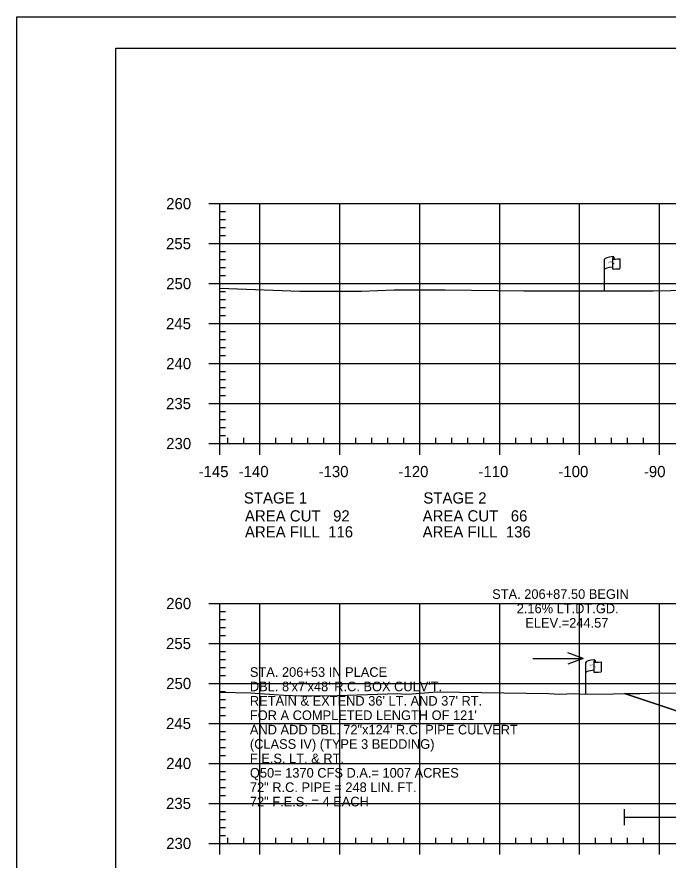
# Model space of a CAD drawing. Extents: x 1365647 to 1367999, y 387113 to 400173.
# Drawn here: x 1365723.7 to 1365805.2, y 390254 to 390359.5 of the extents above; entities that cross this region are included whole.
import ezdxf

# ---------------------------------------------------------------- set-up
doc = ezdxf.new("R2010")
doc.units = 0
for name, color, linetype in [('E_Existing ROW', 7, 'Continuous'), ('R_Axis', 7, 'Continuous'), ('R_Axis Annot', 7, 'Continuous'), ('R_Border', 7, 'Continuous'), ('R_Contours', 7, 'Continuous'), ('R_Draft', 7, 'Continuous'), ('R_Exist Surface', 7, 'Continuous'), ('R_Fin Surface', 7, 'Continuous'), ('R_Grid', 7, 'Continuous'), ('R_No Plot', 7, 'Continuous'), ('R_Proposed Const Limits', 7, 'Continuous'), ('R_Water', 7, 'Continuous'), ('R_Water Annot', 7, 'Continuous')]:
    doc.layers.add(name, color=color, linetype=linetype)

msp = doc.modelspace()

# ---------------------------------------------------------------- linework, layer by layer
at = {"layer": 'E_Existing ROW'}
for p, q in [((1365798.2, 390329.26), (1365798.2, 390329.24)), ((1365798.2, 390329.24), (1365798.2, 390328.02)), ((1365798.36, 390329.41), (1365798.36, 390329.17)), ((1365799.13, 390329.22), (1365799.13, 390327.98)), ((1365797.2, 390325.21), (1365797.2, 390329.16)), ((1365794.85, 390274.8), (1365794.85, 390278.75)), ((1365795.85, 390278.84), (1365795.85, 390278.83)), ((1365795.85, 390278.83), (1365795.85, 390277.6)), ((1365796.02, 390279), (1365796.02, 390278.76)), ((1365796.78, 390278.81), (1365796.78, 390277.57))]:
    msp.add_line(p, q, dxfattribs=at)
for centre, radius, start, end in [((1365798.27, 390329.26), 0.078, 88.6458, 274.2828), ((1365798.29, 390329.41), 0.0783, 263.0712, 93.9564), ((1365798.27, 390328.02), 0.0783, 180, 273.9564), ((1365795.93, 390278.85), 0.078, 88.6458, 274.2828), ((1365795.94, 390279), 0.0783, 263.0712, 93.9564), ((1365795.93, 390277.6), 0.0783, 180, 273.9564)]:
    msp.add_arc(centre, radius, start, end, dxfattribs=at)
for centre, major_axis, ratio, start_param, end_param in [((1365798.78, 390329.2), (-1.58, -0.04), 0.19887, 5.030368, 6.283185), ((1365799.49, 390329.32), (-1.23, -0.13), 0.052933, 0.159456, 1.268315), ((1365798.78, 390327.89), (-1.58, -0.04), 0.19887, 5.083035, 6.194897), ((1365799.49, 390328.08), (-1.23, -0.13), 0.052933, 0.159456, 1.268315), ((1365796.44, 390278.79), (-1.58, -0.04), 0.19887, 5.030368, 6.283185), ((1365797.14, 390278.91), (-1.23, -0.13), 0.052933, 0.159456, 1.268315), ((1365796.43, 390277.48), (-1.58, -0.04), 0.19887, 5.083035, 6.194897), ((1365797.14, 390277.67), (-1.23, -0.13), 0.052933, 0.159456, 1.268315)]:
    msp.add_ellipse(centre, major_axis=major_axis, ratio=ratio, start_param=start_param, end_param=end_param, dxfattribs=at)
at = {"layer": 'R_Axis'}
for p, q in [((1365747.69, 390336.11), (1365749.09, 390336.11)), ((1365749.09, 390306.11), (1365749.09, 390336.11)), ((1365749.09, 390335.11), (1365749.79, 390335.11)), ((1365749.09, 390334.11), (1365749.79, 390334.11)), ((1365749.09, 390333.11), (1365749.79, 390333.11)), ((1365749.09, 390332.11), (1365749.79, 390332.11)), ((1365747.69, 390331.11), (1365749.09, 390331.11)), ((1365749.09, 390330.11), (1365749.79, 390330.11)), ((1365749.09, 390329.11), (1365749.79, 390329.11)), ((1365749.09, 390328.11), (1365749.79, 390328.11)), ((1365749.09, 390327.11), (1365749.79, 390327.11)), ((1365747.69, 390326.11), (1365749.09, 390326.11)), ((1365749.09, 390325.11), (1365749.79, 390325.11)), ((1365749.09, 390324.11), (1365749.79, 390324.11)), ((1365749.09, 390323.11), (1365749.79, 390323.11)), ((1365749.09, 390322.11), (1365749.79, 390322.11)), ((1365747.69, 390321.11), (1365749.09, 390321.11)), ((1365749.09, 390320.11), (1365749.79, 390320.11)), ((1365749.09, 390319.11), (1365749.79, 390319.11)), ((1365749.09, 390318.11), (1365749.79, 390318.11)), ((1365749.09, 390317.11), (1365749.79, 390317.11)), ((1365747.69, 390316.11), (1365749.09, 390316.11)), ((1365749.09, 390315.11), (1365749.79, 390315.11)), ((1365749.09, 390314.11), (1365749.79, 390314.11)), ((1365749.09, 390313.11), (1365749.79, 390313.11)), ((1365749.09, 390312.11), (1365749.79, 390312.11)), ((1365747.69, 390311.11), (1365749.09, 390311.11)), ((1365749.09, 390310.11), (1365749.79, 390310.11)), ((1365749.09, 390309.11), (1365749.79, 390309.11)), ((1365749.09, 390308.11), (1365749.79, 390308.11)), ((1365749.09, 390307.11), (1365749.79, 390307.11)), ((1365747.69, 390306.11), (1365749.09, 390306.11)), ((1365749.09, 390306.11), (1365749.09, 390306.81)), ((1365749.09, 390306.11), (1366039.09, 390306.11)), ((1365749.09, 390304.71), (1365749.09, 390306.11)), ((1365750.09, 390306.11), (1365750.09, 390306.81)), ((1365752.09, 390306.11), (1365752.09, 390306.81)), ((1365754.09, 390304.71), (1365754.09, 390306.11)), ((1365756.09, 390306.11), (1365756.09, 390306.81)), ((1365758.09, 390306.11), (1365758.09, 390306.81)), ((1365760.09, 390306.11), (1365760.09, 390306.81)), ((1365762.09, 390306.11), (1365762.09, 390306.81)), ((1365764.09, 390304.71), (1365764.09, 390306.11)), ((1365766.09, 390306.11), (1365766.09, 390306.81)), ((1365768.09, 390306.11), (1365768.09, 390306.81)), ((1365770.09, 390306.11), (1365770.09, 390306.81)), ((1365772.09, 390306.11), (1365772.09, 390306.81)), ((1365774.09, 390304.71), (1365774.09, 390306.11)), ((1365776.09, 390306.11), (1365776.09, 390306.81)), ((1365778.09, 390306.11), (1365778.09, 390306.81)), ((1365780.09, 390306.11), (1365780.09, 390306.81)), ((1365782.09, 390306.11), (1365782.09, 390306.81)), ((1365784.09, 390304.71), (1365784.09, 390306.11)), ((1365786.09, 390306.11), (1365786.09, 390306.81)), ((1365788.09, 390306.11), (1365788.09, 390306.81)), ((1365790.09, 390306.11), (1365790.09, 390306.81)), ((1365792.09, 390306.11), (1365792.09, 390306.81)), ((1365794.09, 390304.71), (1365794.09, 390306.11)), ((1365796.09, 390306.11), (1365796.09, 390306.81)), ((1365798.09, 390306.11), (1365798.09, 390306.81)), ((1365800.09, 390306.11), (1365800.09, 390306.81)), ((1365802.09, 390306.11), (1365802.09, 390306.81)), ((1365804.09, 390304.71), (1365804.09, 390306.11)), ((1365747.69, 390286.11), (1365749.09, 390286.11)), ((1365749.09, 390256.11), (1365749.09, 390286.11)), ((1365749.09, 390285.11), (1365749.79, 390285.11)), ((1365749.09, 390284.11), (1365749.79, 390284.11)), ((1365749.09, 390283.11), (1365749.79, 390283.11)), ((1365749.09, 390282.11), (1365749.79, 390282.11)), ((1365747.69, 390281.11), (1365749.09, 390281.11)), ((1365749.09, 390280.11), (1365749.79, 390280.11)), ((1365749.09, 390279.11), (1365749.79, 390279.11)), ((1365749.09, 390278.11), (1365749.79, 390278.11)), ((1365749.09, 390277.11), (1365749.79, 390277.11)), ((1365747.69, 390276.11), (1365749.09, 390276.11)), ((1365749.09, 390275.11), (1365749.79, 390275.11)), ((1365749.09, 390274.11), (1365749.79, 390274.11)), ((1365749.09, 390273.11), (1365749.79, 390273.11)), ((1365749.09, 390272.11), (1365749.79, 390272.11)), ((1365747.69, 390271.11), (1365749.09, 390271.11)), ((1365749.09, 390270.11), (1365749.79, 390270.11)), ((1365749.09, 390269.11), (1365749.79, 390269.11)), ((1365749.09, 390268.11), (1365749.79, 390268.11)), ((1365749.09, 390267.11), (1365749.79, 390267.11)), ((1365747.69, 390266.11), (1365749.09, 390266.11)), ((1365749.09, 390265.11), (1365749.79, 390265.11)), ((1365749.09, 390264.11), (1365749.79, 390264.11)), ((1365749.09, 390263.11), (1365749.79, 390263.11)), ((1365749.09, 390262.11), (1365749.79, 390262.11)), ((1365747.69, 390261.11), (1365749.09, 390261.11)), ((1365749.09, 390260.11), (1365749.79, 390260.11)), ((1365749.09, 390259.11), (1365749.79, 390259.11)), ((1365749.09, 390258.11), (1365749.79, 390258.11)), ((1365749.09, 390257.11), (1365749.79, 390257.11)), ((1365749.09, 390256.11), (1365749.09, 390256.81)), ((1365750.09, 390256.11), (1365750.09, 390256.81)), ((1365752.09, 390256.11), (1365752.09, 390256.81)), ((1365756.09, 390256.11), (1365756.09, 390256.81)), ((1365758.09, 390256.11), (1365758.09, 390256.81)), ((1365760.09, 390256.11), (1365760.09, 390256.81)), ((1365762.09, 390256.11), (1365762.09, 390256.81)), ((1365766.09, 390256.11), (1365766.09, 390256.81)), ((1365768.09, 390256.11), (1365768.09, 390256.81)), ((1365770.09, 390256.11), (1365770.09, 390256.81)), ((1365772.09, 390256.11), (1365772.09, 390256.81)), ((1365776.09, 390256.11), (1365776.09, 390256.81)), ((1365778.09, 390256.11), (1365778.09, 390256.81)), ((1365780.09, 390256.11), (1365780.09, 390256.81)), ((1365782.09, 390256.11), (1365782.09, 390256.81)), ((1365786.09, 390256.11), (1365786.09, 390256.81)), ((1365788.09, 390256.11), (1365788.09, 390256.81)), ((1365790.09, 390256.11), (1365790.09, 390256.81)), ((1365792.09, 390256.11), (1365792.09, 390256.81)), ((1365796.09, 390256.11), (1365796.09, 390256.81)), ((1365798.09, 390256.11), (1365798.09, 390256.81)), ((1365800.09, 390256.11), (1365800.09, 390256.81)), ((1365802.09, 390256.11), (1365802.09, 390256.81)), ((1365747.69, 390256.11), (1365749.09, 390256.11)), ((1365749.09, 390256.11), (1366039.09, 390256.11)), ((1365749.09, 390254.71), (1365749.09, 390256.11)), ((1365754.09, 390254.71), (1365754.09, 390256.11)), ((1365764.09, 390254.71), (1365764.09, 390256.11)), ((1365774.09, 390254.71), (1365774.09, 390256.11)), ((1365784.09, 390254.71), (1365784.09, 390256.11)), ((1365794.09, 390254.71), (1365794.09, 390256.11)), ((1365804.09, 390254.71), (1365804.09, 390256.11))]:
    msp.add_line(p, q, dxfattribs=at)
at = {"layer": 'R_Border'}
for p, q in [((1365736.09, 390355.57), (1366052.27, 390355.57)), ((1365736.09, 390150.11), (1365736.09, 390355.57))]:
    msp.add_line(p, q, dxfattribs=at)
at = {"layer": 'R_Contours'}
msp.add_lwpolyline([(1365799.71, 390274.84), (1365801.63, 390274.86), (1365802.89, 390274.88), (1365810.01, 390274.95), (1365810.24, 390274.94), (1365812.7, 390274.77), (1365813.72, 390274.73), (1365819.73, 390274.44), (1365821.58, 390273.81), (1365812.19, 390270.68)], close=True, dxfattribs=at)
at = {"layer": 'R_Exist Surface'}
for points in [[(1365749.09, 390325.54), (1365759.09, 390325.16), (1365766.79, 390325.15), (1365770.91, 390325.32), (1365777.27, 390325.35), (1365787.12, 390325.2), (1365787.37, 390325.2), (1365788.2, 390325.21), (1365794.55, 390325.22), (1365800.55, 390325.19), (1365803.29, 390325.21), (1365812.1, 390325.39)], [(1365749.09, 390275.04), (1365752.97, 390274.95), (1365754.05, 390274.87), (1365757.12, 390274.63), (1365759.2, 390274.58), (1365760.59, 390274.56), (1365763.81, 390274.61), (1365771.29, 390274.84), (1365772.35, 390274.76), (1365773.09, 390274.83), (1365776.25, 390275.05), (1365790.18, 390274.87), (1365791.63, 390274.79), (1365792.49, 390274.82), (1365793.47, 390274.84), (1365794.06, 390274.82), (1365795.05, 390274.79), (1365801.63, 390274.86), (1365802.89, 390274.88), (1365810.01, 390274.95)]]:
    msp.add_lwpolyline(points, dxfattribs=at)
at = {"layer": 'R_Fin Surface'}
msp.add_lwpolyline([(1365799.71, 390274.84), (1365812.19, 390270.68), (1365833.57, 390277.81), (1365834.57, 390277.8), (1365839.1, 390278.24), (1365856.59, 390279.93), (1365862.59, 390280.17), (1365864.59, 390280.21), (1365894.09, 390280.8), (1365923.59, 390280.21), (1365925.59, 390280.17), (1365931.59, 390279.93), (1365942.2, 390278.38), (1365953.6, 390276.71), (1365954.61, 390276.69), (1365977.78, 390268.97), (1365983.34, 390270.82)], dxfattribs=at)
at = {"layer": 'R_Grid'}
for p, q in [((1365749.09, 390336.11), (1366039.09, 390336.11)), ((1365749.09, 390306.11), (1365749.09, 390336.11)), ((1365754.09, 390306.11), (1365754.09, 390336.11)), ((1365764.09, 390306.11), (1365764.09, 390336.11)), ((1365774.09, 390306.11), (1365774.09, 390336.11)), ((1365784.09, 390306.11), (1365784.09, 390336.11)), ((1365794.09, 390306.11), (1365794.09, 390336.11)), ((1365804.09, 390306.11), (1365804.09, 390336.11)), ((1365749.09, 390331.11), (1366039.09, 390331.11)), ((1365749.09, 390326.11), (1366039.09, 390326.11)), ((1365749.09, 390321.11), (1366039.09, 390321.11)), ((1365749.09, 390316.11), (1366039.09, 390316.11)), ((1365749.09, 390311.11), (1366039.09, 390311.11)), ((1365749.09, 390306.11), (1366039.09, 390306.11)), ((1365749.09, 390286.11), (1366039.09, 390286.11)), ((1365749.09, 390256.11), (1365749.09, 390286.11)), ((1365754.09, 390256.11), (1365754.09, 390286.11)), ((1365764.09, 390256.11), (1365764.09, 390286.11)), ((1365774.09, 390256.11), (1365774.09, 390286.11)), ((1365784.09, 390256.11), (1365784.09, 390286.11)), ((1365794.09, 390256.11), (1365794.09, 390286.11)), ((1365804.09, 390256.11), (1365804.09, 390286.11)), ((1365749.09, 390281.11), (1366039.09, 390281.11)), ((1365749.09, 390276.11), (1366039.09, 390276.11)), ((1365749.09, 390271.11), (1366039.09, 390271.11)), ((1365749.09, 390266.11), (1366039.09, 390266.11)), ((1365749.09, 390261.11), (1366039.09, 390261.11)), ((1365749.09, 390256.11), (1366039.09, 390256.11))]:
    msp.add_line(p, q, dxfattribs=at)
at = {"layer": 'R_No Plot'}
msp.add_line((1365723.69, 390359.47), (1366057.03, 390359.47), dxfattribs=at)
msp.add_lwpolyline([(1365723.69, 390359.47), (1366057.03, 390359.47), (1366057.03, 390146.13), (1365723.69, 390146.13)], close=True, dxfattribs=at)
at = {"layer": 'R_Proposed Const Limits'}
msp.add_lwpolyline([(1365799.71, 390274.84), (1365812.19, 390270.68)], dxfattribs=at)
at = {"layer": 'R_Water'}
for p, q in [((1365799.71, 390258.39), (1365799.71, 390260.39)), ((1365799.71, 390259.39), (1365881.8, 390259.39))]:
    msp.add_line(p, q, dxfattribs=at)
at = {"layer": 'R_Water Annot'}
for p, q in [((1365794.53, 390279.24), (1365792.6, 390279.94)), ((1365788.24, 390279.24), (1365794.53, 390279.24)), ((1365794.53, 390279.24), (1365792.6, 390278.54))]:
    msp.add_line(p, q, dxfattribs=at)

# ---------------------------------------------------------------- texts
at = {"layer": 'E_Existing ROW'}
for s, height, rotation, p in [('R ', 0.2, 9.9884, (1365797.72, 390328.66)), (' O', 0.2, 9.9884, (1365797.87, 390328.71)), ('W', 0.2, 351.1788, (1365798.2, 390328.54)), ('DWB 11-9-07', 0.001, 90, (1365798.36, 390329.17)), ('DWB 11-9-07', 0.001, 5.0717, (1365799.12, 390327.98)), ('DWB 11-9-07', 0.001, 90, (1365797.2, 390325.21)), ('DWB 11-9-07', 0.001, 90, (1365796.02, 390278.76)), ('R ', 0.2, 9.9884, (1365795.37, 390278.25)), (' O', 0.2, 9.9884, (1365795.52, 390278.3)), ('W', 0.2, 351.1788, (1365795.85, 390278.13)), ('DWB 11-9-07', 0.001, 5.0717, (1365796.77, 390277.57)), ('DWB 11-9-07', 0.001, 90, (1365794.85, 390274.8))]:
    msp.add_text(s, height=height, rotation=rotation, dxfattribs=at).set_placement(p)
at = {"layer": 'R_Axis Annot'}
for s, p in [('260', (1365742.37, 390335.41)), ('255', (1365742.35, 390330.41)), ('250', (1365742.37, 390325.41)), ('245', (1365742.35, 390320.41)), ('240', (1365742.37, 390315.41)), ('235', (1365742.35, 390310.41)), ('230', (1365742.37, 390305.41)), ('-145', (1365746.42, 390301.91)), ('-140', (1365751.43, 390301.91)), ('-130', (1365761.43, 390301.91)), ('-120', (1365771.43, 390301.91)), ('-110', (1365781.43, 390301.91)), ('-100', (1365791.43, 390301.91)), ('-90', (1365802.13, 390301.91)), ('STAGE 1', (1365752.09, 390298.61)), ('STAGE 2', (1365774.54, 390298.61)), ('AREA CUT   92', (1365752.22, 390296.37)), ('AREA CUT   66', (1365774.45, 390296.37)), ('AREA FILL  116', (1365752.22, 390294.37)), ('AREA FILL  136', (1365774.45, 390294.37)), ('260', (1365742.37, 390285.41)), ('255', (1365742.35, 390280.41)), ('250', (1365742.37, 390275.41)), ('245', (1365742.35, 390270.41)), ('240', (1365742.37, 390265.41)), ('235', (1365742.35, 390260.41)), ('230', (1365742.37, 390255.41))]:
    msp.add_text(s, height=1.4, dxfattribs=at).set_placement(p)
at = {"layer": 'R_Draft'}
for s, p in [('STA. 206+53 IN PLACE', (1365752.84, 390276.94)), ("DBL. 8'x7'x48' R.C. BOX CULV'T.", (1365752.84, 390275.14)), ("RETAIN & EXTEND 36' LT. AND 37' RT.", (1365752.84, 390273.34)), ("FOR A COMPLETED LENGTH OF 121'", (1365752.84, 390271.54)), ('AND ADD DBL. 72"x124\' R.C. PIPE CULVERT', (1365752.84, 390269.74)), ('(CLASS IV) (TYPE 3 BEDDING)', (1365752.84, 390267.94)), ('F.E.S. LT. & RT.', (1365752.84, 390266.14)), ('Q50= 1370 CFS D.A.= 1007 ACRES', (1365752.84, 390264.34)), ('72" R.C. PIPE = 248 LIN. FT.', (1365752.84, 390262.54)), ('72" F.E.S. = 4 EACH', (1365752.84, 390260.74))]:
    msp.add_text(s, height=1.2, rotation=360, dxfattribs=at).set_placement(p)
at = {"layer": 'R_Water'}
for s, p in [('STA. 206+87.50 BEGIN ', (1365783.15, 390286.69)), ('2.16% LT.DT.GD.', (1365786.22, 390284.89)), ('ELEV.=244.57', (1365787.3, 390283.09))]:
    msp.add_text(s, height=1.2, dxfattribs=at).set_placement(p)

doc.saveas('drawing.dxf')
